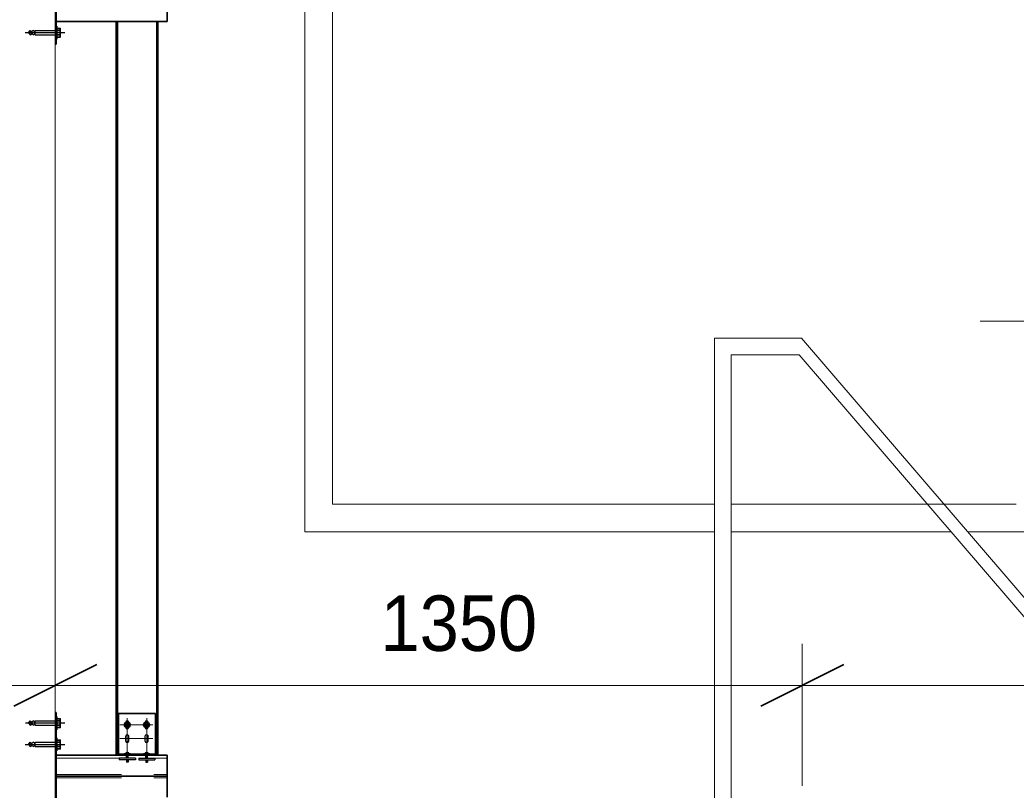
# Model space of a CAD drawing. Extents: x -4160 to -2690, y -474 to 714.
# Drawn here: x -3669.09 to -3643.41, y -322.51 to -302.66 of the extents above; entities that cross this region are included whole.
import ezdxf
from ezdxf.enums import TextEntityAlignment as Align

# ---------------------------------------------------------------- set-up
doc = ezdxf.new("R2010")
doc.units = 0
doc.header["$LTSCALE"] = 0.56
doc.linetypes.add('DOT_DASHED', pattern=[7.7, 5, -1.2, 0.3, -1.2])
doc.linetypes.add('MEDIUM_DASHED', pattern=[4.5, 3, -1.5])
for name, color, linetype, lineweight in [('10', 7, 'Continuous', 35), ('11', 7, 'Continuous', 13), ('2', 7, 'Continuous', 25), ('20', 7, 'Continuous', 13), ('3', 7, 'Continuous', 13), ('5', 7, 'Continuous', 35), ('6', 7, 'Continuous', 35)]:
    doc.layers.add(name, color=color, linetype=linetype, lineweight=lineweight)

msp = doc.modelspace()

# ---------------------------------------------------------------- linework, layer by layer
at = {"layer": '10', "linetype": 'MEDIUM_DASHED', "lineweight": 25}
for p, q in [((-3668.9513, -302.9855), (-3667.927, -302.9855)), ((-3668.867, -302.9855), (-3668.8198, -302.9283)), ((-3668.867, -302.9855), (-3668.8198, -303.0412)), ((-3668.8198, -303.0412), (-3668.8198, -302.9283)), ((-3668.8198, -302.9283), (-3668.7798, -302.9583)), ((-3668.7398, -302.9283), (-3668.7798, -302.9583)), ((-3668.7798, -303.0169), (-3668.7798, -302.9583)), ((-3668.7398, -302.9283), (-3668.7027, -302.9583)), ((-3668.7027, -303.0169), (-3668.7027, -302.9583)), ((-3668.7027, -302.9583), (-3668.6956, -302.9583)), ((-3668.6956, -302.9283), (-3668.1556, -302.9283)), ((-3668.6956, -302.9583), (-3668.6956, -302.9283)), ((-3668.6956, -303.0169), (-3668.6956, -302.9583)), ((-3668.8198, -303.0412), (-3668.7798, -303.0169)), ((-3668.7398, -303.0412), (-3668.7798, -303.0169)), ((-3668.7398, -303.0412), (-3668.7027, -303.0169)), ((-3668.7027, -303.0169), (-3668.6956, -303.0169)), ((-3668.6956, -303.0412), (-3668.6956, -303.0169)), ((-3668.6956, -303.0412), (-3668.1556, -303.0412)), ((-3667.927, -320.784), (-3668.9441, -320.784)), ((-3668.867, -320.784), (-3668.8198, -320.7269)), ((-3668.867, -320.784), (-3668.8198, -320.8412)), ((-3668.8198, -320.8412), (-3668.8198, -320.7269)), ((-3668.8198, -320.7269), (-3668.7798, -320.7583)), ((-3668.8198, -320.8412), (-3668.7798, -320.8155)), ((-3668.7398, -320.7269), (-3668.7798, -320.7583)), ((-3668.7798, -320.8155), (-3668.7798, -320.7583)), ((-3668.7398, -320.8412), (-3668.7798, -320.8155)), ((-3668.7398, -320.7269), (-3668.7027, -320.7583)), ((-3668.7398, -320.8412), (-3668.7027, -320.8155)), ((-3668.7027, -320.8155), (-3668.7027, -320.7583)), ((-3668.7027, -320.7583), (-3668.6956, -320.7583)), ((-3668.7027, -320.8155), (-3668.6956, -320.8155)), ((-3668.6956, -320.7269), (-3668.1556, -320.7269)), ((-3668.6956, -320.7583), (-3668.6956, -320.7269)), ((-3668.6956, -320.8155), (-3668.6956, -320.7583)), ((-3668.6956, -320.8412), (-3668.6956, -320.8155)), ((-3668.6956, -320.8412), (-3668.1556, -320.8412)), ((-3668.9513, -321.3369), (-3667.927, -321.3369)), ((-3668.867, -321.3369), (-3668.8198, -321.2798)), ((-3668.867, -321.3369), (-3668.8198, -321.3926)), ((-3668.8198, -321.3926), (-3668.8198, -321.2798)), ((-3668.8198, -321.2798), (-3668.7798, -321.3069)), ((-3668.8198, -321.3926), (-3668.7798, -321.3683)), ((-3668.7398, -321.2798), (-3668.7798, -321.3069)), ((-3668.7798, -321.3683), (-3668.7798, -321.3069)), ((-3668.7398, -321.3926), (-3668.7798, -321.3683)), ((-3668.7398, -321.2798), (-3668.7027, -321.3069)), ((-3668.7398, -321.3926), (-3668.7027, -321.3683)), ((-3668.7027, -321.3683), (-3668.7027, -321.3069)), ((-3668.7027, -321.3069), (-3668.6956, -321.3069)), ((-3668.7027, -321.3683), (-3668.6956, -321.3683)), ((-3668.6956, -321.2798), (-3668.1556, -321.2798)), ((-3668.6956, -321.3069), (-3668.6956, -321.2798)), ((-3668.6956, -321.3683), (-3668.6956, -321.3069)), ((-3668.6956, -321.3926), (-3668.6956, -321.3683)), ((-3668.6956, -321.3926), (-3668.1556, -321.3926))]:
    msp.add_line(p, q, dxfattribs=at)
at = {"layer": '10'}
for p, q in [((-3668.1527, -303.1541), (-3668.1527, -302.8155)), ((-3668.137, -302.8155), (-3668.1527, -302.8155)), ((-3668.137, -303.1541), (-3668.137, -302.8155)), ((-3668.137, -303.1326), (-3668.137, -302.9083)), ((-3668.0598, -302.9283), (-3668.137, -302.9283)), ((-3668.0598, -302.8741), (-3668.0498, -302.8926)), ((-3668.0598, -302.9283), (-3668.0498, -302.9083)), ((-3668.0598, -302.9283), (-3668.0498, -302.9526)), ((-3668.137, -303.1541), (-3668.1527, -303.1541)), ((-3668.0598, -303.0398), (-3668.137, -303.0398)), ((-3668.0598, -303.0412), (-3668.0498, -303.0212)), ((-3668.0598, -303.0412), (-3668.0498, -303.0655)), ((-3668.0598, -303.0998), (-3668.0498, -303.0712)), ((-3668.1756, -303.2826), (-3668.1527, -303.2826)), ((-3668.1756, -320.5083), (-3668.1527, -320.5083)), ((-3668.1527, -320.9555), (-3668.1527, -320.6155)), ((-3668.137, -320.6155), (-3668.1527, -320.6155)), ((-3668.137, -320.9555), (-3668.137, -320.6155)), ((-3668.137, -320.934), (-3668.137, -320.7055)), ((-3668.0598, -320.6726), (-3668.0498, -320.6926)), ((-3668.0598, -320.7269), (-3668.0498, -320.7098)), ((-3668.137, -320.9555), (-3668.1527, -320.9555)), ((-3668.0598, -320.7269), (-3668.137, -320.7269)), ((-3668.0598, -320.8412), (-3668.137, -320.8412)), ((-3668.0598, -320.7269), (-3668.0498, -320.7526)), ((-3668.0598, -320.8412), (-3668.0498, -320.8198)), ((-3668.0598, -320.8412), (-3668.0498, -320.8669)), ((-3668.0598, -320.9012), (-3668.0498, -320.8726)), ((-3668.1527, -321.504), (-3668.1527, -321.1655)), ((-3668.137, -321.1655), (-3668.1527, -321.1655)), ((-3668.137, -321.504), (-3668.137, -321.1655)), ((-3668.0598, -321.2226), (-3668.0498, -321.2426)), ((-3668.137, -321.484), (-3668.137, -321.2555)), ((-3668.0598, -321.2798), (-3668.137, -321.2798)), ((-3668.0598, -321.3912), (-3668.137, -321.3912)), ((-3668.0598, -321.2798), (-3668.0498, -321.2569)), ((-3668.0598, -321.2798), (-3668.0498, -321.304)), ((-3668.0598, -321.3926), (-3668.0498, -321.3698)), ((-3668.0598, -321.3926), (-3668.0498, -321.4155)), ((-3668.0598, -321.4498), (-3668.0498, -321.4226)), ((-3668.137, -321.504), (-3668.1527, -321.504)), ((-3666.2384, -321.574), (-3666.3998, -321.574)), ((-3666.3998, -321.574), (-3666.3998, -321.584)), ((-3666.2384, -321.584), (-3666.3998, -321.584)), ((-3666.2727, -321.5726), (-3666.3656, -321.5726)), ((-3666.3241, -321.5555), (-3666.3241, -321.5426)), ((-3666.3141, -321.5555), (-3666.3241, -321.5555)), ((-3666.3141, -321.5555), (-3666.3141, -321.5426)), ((-3666.2384, -321.574), (-3666.2384, -321.584)), ((-3665.8984, -321.574), (-3665.737, -321.574)), ((-3665.8984, -321.574), (-3665.8984, -321.584)), ((-3665.8984, -321.584), (-3665.737, -321.584)), ((-3665.8641, -321.5726), (-3665.7713, -321.5726)), ((-3665.8227, -321.5555), (-3665.8227, -321.5426)), ((-3665.8227, -321.5555), (-3665.8127, -321.5555)), ((-3665.8127, -321.5555), (-3665.8127, -321.5426)), ((-3665.737, -321.574), (-3665.737, -321.584))]:
    msp.add_line(p, q, dxfattribs=at)
at = {"layer": '10', "lineweight": 13}
for p, q in [((-3651.1799, -310.8583), (-3651.1799, -326.5726)), ((-3651.1799, -310.8583), (-3648.937, -310.8583)), ((-3648.937, -310.8583), (-3641.3556, -319.704)), ((-3650.7513, -326.5726), (-3650.7513, -311.2869)), ((-3650.7513, -311.2869), (-3648.9984, -311.2869)), ((-3648.9984, -311.2869), (-3641.4127, -320.1355))]:
    msp.add_line(p, q, dxfattribs=at)
at = {"layer": '10', "lineweight": 25}
for p, q in [((-3666.3584, -320.7598), (-3666.3584, -320.764)), ((-3666.3584, -320.8983), (-3666.3584, -320.894)), ((-3666.2827, -320.764), (-3666.2827, -320.7598)), ((-3666.2827, -320.894), (-3666.2827, -320.8983)), ((-3665.8613, -320.764), (-3665.8613, -320.7598)), ((-3665.8613, -320.894), (-3665.8613, -320.8983)), ((-3665.7856, -320.7598), (-3665.7856, -320.764)), ((-3665.7856, -320.8983), (-3665.7856, -320.894)), ((-3666.3584, -321.114), (-3666.3584, -321.1183)), ((-3666.2827, -321.1183), (-3666.2827, -321.114)), ((-3666.2827, -321.2498), (-3666.2827, -321.1183)), ((-3665.8613, -321.1183), (-3665.8613, -321.114)), ((-3665.8613, -321.2498), (-3665.8613, -321.1183)), ((-3665.7856, -321.114), (-3665.7856, -321.1183)), ((-3666.2827, -321.2498), (-3666.2827, -321.254)), ((-3665.8613, -321.2498), (-3665.8613, -321.254))]:
    msp.add_line(p, q, dxfattribs=at)
at = {"layer": '10'}
for points in [[(-3668.137, -302.8741), (-3668.0498, -302.8741), (-3668.0498, -303.0998), (-3668.137, -303.0998)], [(-3668.137, -320.6726), (-3668.0498, -320.6726), (-3668.0498, -320.9012), (-3668.137, -320.9012)], [(-3668.137, -321.2226), (-3668.0498, -321.2226), (-3668.0498, -321.4498), (-3668.137, -321.4498)]]:
    msp.add_lwpolyline(points, dxfattribs=at)
for points in [[(-3666.3713, -320.8298), (-3666.3456, -320.7855), (-3666.2941, -320.7855), (-3666.2698, -320.8298), (-3666.2941, -320.874), (-3666.3456, -320.874)], [(-3665.7727, -320.8298), (-3665.7984, -320.7855), (-3665.8484, -320.7855), (-3665.8741, -320.8298), (-3665.8484, -320.874), (-3665.7984, -320.874)]]:
    msp.add_lwpolyline(points, close=True, dxfattribs=at)
at = {"layer": '10', "lineweight": 25}
for points in [[(-3666.3584, -321.254), (-3666.3584, -321.2498), (-3666.3584, -321.1183)], [(-3665.7856, -321.254), (-3665.7856, -321.2498), (-3665.7856, -321.1183)]]:
    msp.add_lwpolyline(points, dxfattribs=at)
at = {"layer": '10'}
for centre, radius in [((-3666.3205, -320.8298), 0.0752), ((-3666.3205, -320.8298), 0.0255), ((-3665.8238, -320.8298), 0.0752), ((-3665.8237, -320.8298), 0.0255)]:
    msp.add_circle(centre, radius, dxfattribs=at)
at = {"layer": '10', "lineweight": 25}
for centre, start, end in [((-3666.3205, -320.7681), 11.60641, 168.39359), ((-3666.3205, -320.8914), 191.60641, 348.39359), ((-3665.8238, -320.7681), 11.60641, 168.39359), ((-3665.8238, -320.8914), 191.60641, 348.39359), ((-3666.3205, -321.1229), 11.60641, 168.39359), ((-3665.8238, -321.1229), 11.60641, 168.39359), ((-3666.3205, -321.2463), 191.60641, 348.39359), ((-3665.8238, -321.2463), 191.60641, 348.39359)]:
    msp.add_arc(centre, 0.0391, start, end, dxfattribs=at)
at = {"layer": '10'}
for centre, start, end in [((-3666.3195, -321.5942), 95.02894, 155.65971), ((-3666.3195, -321.5942), 24.34029, 84.97106), ((-3665.8173, -321.5942), 95.02894, 155.65971), ((-3665.8173, -321.5942), 24.34029, 84.97106)]:
    msp.add_arc(centre, 0.0519, start, end, dxfattribs=at)
at = {"layer": '11'}
for p, q in [((-3668.1756, -265.1441), (-3668.1756, -330.144)), ((-3668.1756, -301.5169), (-3668.1756, -308.4298))]:
    msp.add_line(p, q, dxfattribs=at)
at = {"layer": '2', "lineweight": 13}
for p, q in [((-3668.1755, -329.0727), (-3668.1755, -318.7427)), ((-3648.9212, -322.4055), (-3648.9212, -318.7427)), ((-3675.6755, -319.8141), (-3641.4212, -319.8141))]:
    msp.add_line(p, q, dxfattribs=at)
at = {"layer": '2', "lineweight": 35}
for p, q in [((-3667.1041, -319.2784), (-3669.2469, -320.3498)), ((-3649.9926, -320.3498), (-3647.8498, -319.2784))]:
    msp.add_line(p, q, dxfattribs=at)
at = {"layer": '20'}
for p, q in [((-3661.0327, -293.7155), (-3661.0327, -315.1441)), ((-3661.0327, -315.1441), (-3651.1799, -315.1441)), ((-3650.7513, -315.1441), (-3643.4099, -315.1441)), ((-3650.7513, -315.8583), (-3645.0799, -315.8583)), ((-3644.6513, -315.8583), (-3641.3342, -315.8583))]:
    msp.add_line(p, q, dxfattribs=at)
msp.add_lwpolyline([(-3661.747, -293.0012), (-3661.747, -315.8583), (-3651.1799, -315.8583)], dxfattribs=at)
at = {"layer": '3', "lineweight": 35}
for p, q in [((-3666.6041, -302.6984), (-3666.6041, -321.6127)), ((-3666.5755, -302.6956), (-3666.5755, -321.6127)), ((-3665.5612, -302.6984), (-3665.5612, -321.6127)), ((-3665.5326, -302.6984), (-3665.5326, -321.6127))]:
    msp.add_line(p, q, dxfattribs=at)
at = {"layer": '3', "linetype": 'DOT_DASHED'}
for p, q in [((-3666.3198, -320.6541), (-3666.3198, -321.667)), ((-3665.8183, -320.6541), (-3665.8183, -321.5841)), ((-3666.5098, -320.827), (-3665.6612, -320.827)), ((-3666.5098, -321.1841), (-3665.6612, -321.1841)), ((-3666.3583, -321.1841), (-3666.2826, -321.1841)), ((-3665.8612, -321.1841), (-3665.7855, -321.1841))]:
    msp.add_line(p, q, dxfattribs=at)
at = {"layer": '3', "linetype": 'MEDIUM_DASHED', "lineweight": 25}
for p, q in [((-3666.5269, -321.6927), (-3666.5269, -321.7355)), ((-3666.1126, -321.6927), (-3666.5269, -321.6927)), ((-3666.1126, -321.7355), (-3666.5269, -321.7355)), ((-3666.3398, -321.6927), (-3666.3398, -321.6127)), ((-3666.2983, -321.6398), (-3666.3398, -321.6398)), ((-3666.2983, -321.6541), (-3666.3398, -321.6541)), ((-3666.2983, -321.6698), (-3666.3398, -321.6698)), ((-3666.2983, -321.6855), (-3666.3398, -321.6855)), ((-3666.3398, -321.7355), (-3666.3398, -321.7884)), ((-3666.2983, -321.7427), (-3666.3398, -321.7427)), ((-3666.3055, -321.647), (-3666.3326, -321.647)), ((-3666.3055, -321.6627), (-3666.3326, -321.6627)), ((-3666.3055, -321.677), (-3666.3326, -321.677)), ((-3666.2983, -321.6927), (-3666.2983, -321.6127)), ((-3666.2983, -321.7355), (-3666.2983, -321.7884)), ((-3666.1126, -321.6927), (-3666.1126, -321.7355)), ((-3666.0241, -321.6927), (-3666.0241, -321.7355)), ((-3666.0241, -321.6927), (-3665.6098, -321.6927)), ((-3666.0241, -321.7355), (-3665.6098, -321.7355)), ((-3665.8383, -321.6927), (-3665.8383, -321.6127)), ((-3665.8383, -321.6398), (-3665.7969, -321.6398)), ((-3665.8383, -321.6541), (-3665.7969, -321.6541)), ((-3665.8383, -321.6698), (-3665.7969, -321.6698)), ((-3665.8383, -321.6855), (-3665.7969, -321.6855)), ((-3665.8383, -321.7355), (-3665.8383, -321.7884)), ((-3665.8383, -321.7427), (-3665.7969, -321.7427)), ((-3665.8312, -321.647), (-3665.8041, -321.647)), ((-3665.8312, -321.6627), (-3665.8041, -321.6627)), ((-3665.8312, -321.677), (-3665.8041, -321.677)), ((-3665.7969, -321.6927), (-3665.7969, -321.6127)), ((-3665.7969, -321.7355), (-3665.7969, -321.7884)), ((-3665.6098, -321.6927), (-3665.6098, -321.7355)), ((-3666.2983, -321.7584), (-3666.3398, -321.7584)), ((-3666.2983, -321.7741), (-3666.3398, -321.7741)), ((-3666.2983, -321.7884), (-3666.3398, -321.7884)), ((-3666.3055, -321.7513), (-3666.3326, -321.7513)), ((-3666.3055, -321.7655), (-3666.3326, -321.7655)), ((-3666.3055, -321.7813), (-3666.3326, -321.7813)), ((-3665.8383, -321.7584), (-3665.7969, -321.7584)), ((-3665.8383, -321.7741), (-3665.7969, -321.7741)), ((-3665.8383, -321.7884), (-3665.7969, -321.7884)), ((-3665.8312, -321.7513), (-3665.8041, -321.7513)), ((-3665.8312, -321.7655), (-3665.8041, -321.7655)), ((-3665.8312, -321.7813), (-3665.8041, -321.7813))]:
    msp.add_line(p, q, dxfattribs=at)
at = {"layer": '3', "lineweight": 35}
for radius in [5.0714, 6.5]:
    msp.add_arc((-3646.4055, -319.2427), radius, 270, 0, dxfattribs=at)
at = {"layer": '5', "linetype": 'DOT_DASHED', "lineweight": 13}
msp.add_line((-3630.1755, -310.4255), (-3644.3327, -310.4255), dxfattribs=at)
at = {"layer": '6'}
for p, q in [((-3668.1526, -300.5084), (-3668.1526, -303.2827)), ((-3665.2955, -301.6127), (-3665.2955, -302.6984)), ((-3668.1526, -302.6984), (-3665.2955, -302.6984)), ((-3668.1526, -320.5084), (-3668.1526, -323.2827)), ((-3666.5469, -320.5413), (-3666.5469, -321.6127)), ((-3666.5469, -320.5413), (-3665.5898, -320.5413)), ((-3665.5898, -320.5413), (-3665.5898, -321.6127)), ((-3668.1526, -321.6127), (-3665.2955, -321.6127)), ((-3666.5469, -321.5841), (-3665.5898, -321.5841)), ((-3665.2955, -321.6127), (-3665.2955, -322.6984)), ((-3668.1526, -322.1555), (-3665.2955, -322.1555))]:
    msp.add_line(p, q, dxfattribs=at)
at = {"layer": '6', "linetype": 'MEDIUM_DASHED', "lineweight": 13}
for p, q in [((-3668.1526, -321.6927), (-3665.2955, -321.6927)), ((-3668.1526, -322.1113), (-3665.2955, -322.1113)), ((-3668.1526, -322.1998), (-3665.2955, -322.1998))]:
    msp.add_line(p, q, dxfattribs=at)

# ---------------------------------------------------------------- texts
at = {"layer": '2', "width": 0.95}
msp.add_text('1350', height=1.429, dxfattribs=at).set_placement((-3657.7748, -318.9241), align=Align.CENTER)

doc.saveas('drawing.dxf')
